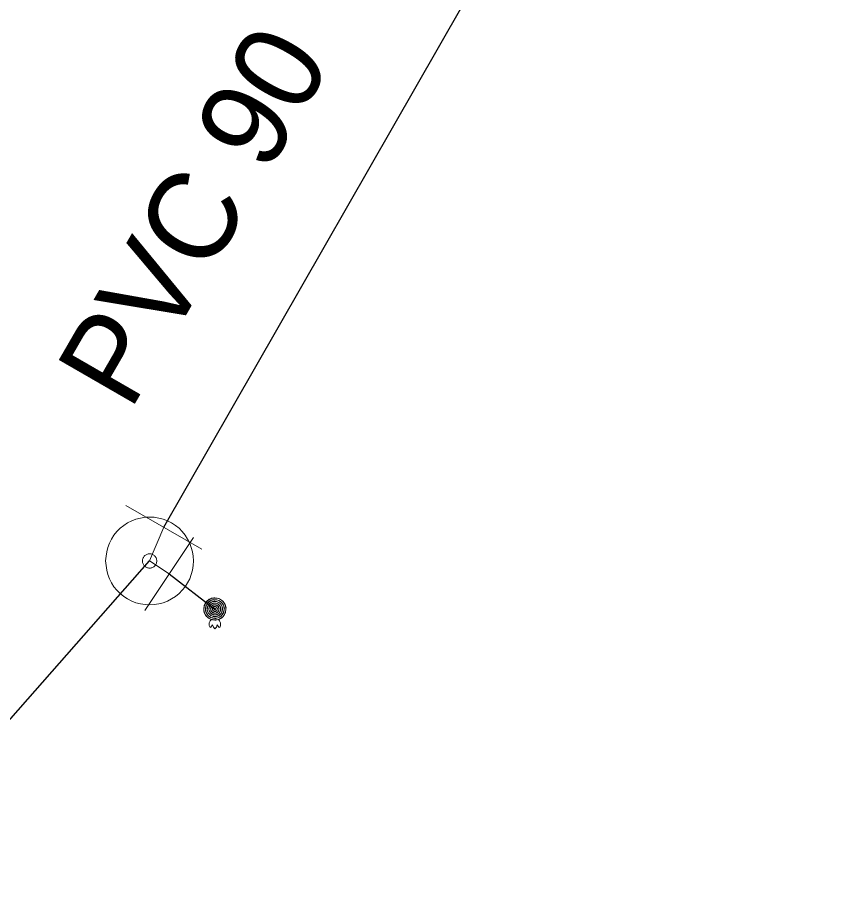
# Model space of a CAD drawing. Extents: x -683466 to -682479, y -996772 to -995963.
# Drawn here: x -682674.1 to -682664.75, y -996500.91 to -996490.91 of the extents above; entities that cross this region are included whole.
import ezdxf

# ---------------------------------------------------------------- set-up
doc = ezdxf.new("R2010")
doc.units = 0
doc.header["$LTSCALE"] = 0.4
doc.layers.add('1', color=7, linetype='Continuous')
for name, color, linetype, lineweight in [('14', 7, 'Continuous', 25), ('17', 7, 'Continuous', 25), ('34', 7, 'Continuous', 13), ('47', 7, 'Continuous', 13), ('9', 7, 'Continuous', 13)]:
    doc.layers.add(name, color=color, linetype=linetype, lineweight=lineweight)

msp = doc.modelspace()

# ---------------------------------------------------------------- linework, layer by layer
at = {"layer": '14', "lineweight": 13}
for q in [(-682672.44, -996496.719), (-682672.379, -996497.25)]:
    msp.add_line((-682672.602, -996497.102), q, dxfattribs=at)
at = {"layer": '17'}
msp.add_line((-682672.379, -996497.25), (-682671.859, -996497.649), dxfattribs=at)
for points in [[(-682672.44, -996496.719), (-682668.522, -996489.866), (-682664.75, -996485.199), (-682666.331, -996484.881)], [(-682688.782, -996515.794), (-682687.14, -996513.631), (-682672.602, -996497.102)]]:
    msp.add_lwpolyline(points, dxfattribs=at)
at = {"layer": '34'}
for p, q in [((-682672.874, -996496.471), (-682672.006, -996496.967)), ((-682672.102, -996496.833), (-682672.656, -996497.665))]:
    msp.add_line(p, q, dxfattribs=at)
at = {"layer": '47'}
for points in [[(-682672.102, -996497.102), (-682672.105, -996497.049), (-682672.113, -996496.997), (-682672.127, -996496.948), (-682672.144, -996496.899), (-682672.169, -996496.852), (-682672.198, -996496.808), (-682672.23, -996496.767), (-682672.267, -996496.73), (-682672.308, -996496.698), (-682672.352, -996496.669), (-682672.399, -996496.644), (-682672.448, -996496.627), (-682672.497, -996496.613), (-682672.549, -996496.605), (-682672.602, -996496.602), (-682672.654, -996496.605), (-682672.706, -996496.613), (-682672.757, -996496.627), (-682672.804, -996496.644), (-682672.852, -996496.669), (-682672.896, -996496.698), (-682672.936, -996496.73), (-682672.973, -996496.767), (-682673.007, -996496.808), (-682673.034, -996496.852), (-682673.059, -996496.899), (-682673.078, -996496.948), (-682673.09, -996496.997), (-682673.098, -996497.049), (-682673.102, -996497.102), (-682673.098, -996497.154), (-682673.09, -996497.206), (-682673.078, -996497.257), (-682673.059, -996497.304), (-682673.034, -996497.352), (-682673.007, -996497.396), (-682672.973, -996497.436), (-682672.936, -996497.473), (-682672.896, -996497.507), (-682672.852, -996497.534), (-682672.804, -996497.559), (-682672.757, -996497.578), (-682672.706, -996497.59), (-682672.654, -996497.598), (-682672.602, -996497.602), (-682672.549, -996497.598), (-682672.497, -996497.59), (-682672.448, -996497.578), (-682672.399, -996497.559), (-682672.352, -996497.534), (-682672.308, -996497.507), (-682672.267, -996497.473), (-682672.23, -996497.436), (-682672.198, -996497.396), (-682672.169, -996497.352), (-682672.144, -996497.304), (-682672.127, -996497.257), (-682672.113, -996497.206), (-682672.105, -996497.154)], [(-682672.519, -996497.102), (-682672.519, -996497.093), (-682672.522, -996497.085), (-682672.524, -996497.076), (-682672.527, -996497.068), (-682672.531, -996497.061), (-682672.536, -996497.054), (-682672.541, -996497.046), (-682672.546, -996497.041), (-682672.554, -996497.036), (-682672.561, -996497.031), (-682672.568, -996497.027), (-682672.576, -996497.024), (-682672.585, -996497.022), (-682672.593, -996497.019), (-682672.602, -996497.019), (-682672.61, -996497.019), (-682672.619, -996497.022), (-682672.627, -996497.024), (-682672.635, -996497.027), (-682672.642, -996497.031), (-682672.649, -996497.036), (-682672.657, -996497.041), (-682672.663, -996497.046), (-682672.669, -996497.054), (-682672.673, -996497.061), (-682672.676, -996497.068), (-682672.679, -996497.076), (-682672.681, -996497.085), (-682672.684, -996497.093), (-682672.684, -996497.102), (-682672.684, -996497.11), (-682672.681, -996497.119), (-682672.679, -996497.127), (-682672.676, -996497.135), (-682672.673, -996497.142), (-682672.669, -996497.149), (-682672.663, -996497.157), (-682672.657, -996497.163), (-682672.649, -996497.169), (-682672.642, -996497.173), (-682672.635, -996497.176), (-682672.627, -996497.179), (-682672.619, -996497.181), (-682672.61, -996497.184), (-682672.602, -996497.184), (-682672.593, -996497.184), (-682672.585, -996497.181), (-682672.576, -996497.179), (-682672.568, -996497.176), (-682672.561, -996497.173), (-682672.554, -996497.169), (-682672.546, -996497.163), (-682672.541, -996497.157), (-682672.536, -996497.149), (-682672.531, -996497.142), (-682672.527, -996497.135), (-682672.524, -996497.127), (-682672.522, -996497.119), (-682672.519, -996497.11)]]:
    msp.add_lwpolyline(points, close=True, dxfattribs=at)
at = {"layer": '9'}
for points in [[(-682671.859, -996497.522), (-682671.872, -996497.522), (-682671.885, -996497.524), (-682671.898, -996497.527), (-682671.91, -996497.532), (-682671.922, -996497.538), (-682671.933, -996497.545), (-682671.943, -996497.553), (-682671.953, -996497.563), (-682671.961, -996497.573), (-682671.968, -996497.584), (-682671.974, -996497.596), (-682671.979, -996497.608), (-682671.982, -996497.621), (-682671.984, -996497.634), (-682671.986, -996497.647), (-682671.985, -996497.66), (-682671.983, -996497.673), (-682671.98, -996497.686), (-682671.975, -996497.698), (-682671.969, -996497.71), (-682671.962, -996497.721), (-682671.954, -996497.731), (-682671.944, -996497.741), (-682671.934, -996497.749), (-682671.923, -996497.756), (-682671.911, -996497.762), (-682671.899, -996497.767), (-682671.886, -996497.77), (-682671.873, -996497.772), (-682671.86, -996497.774), (-682671.847, -996497.774), (-682671.834, -996497.772), (-682671.821, -996497.769), (-682671.809, -996497.764), (-682671.797, -996497.758), (-682671.786, -996497.751), (-682671.776, -996497.743), (-682671.766, -996497.733), (-682671.758, -996497.723), (-682671.751, -996497.712), (-682671.745, -996497.7), (-682671.74, -996497.688), (-682671.737, -996497.675), (-682671.735, -996497.662), (-682671.734, -996497.649), (-682671.734, -996497.636), (-682671.736, -996497.623), (-682671.739, -996497.61), (-682671.744, -996497.598), (-682671.75, -996497.586), (-682671.757, -996497.575), (-682671.765, -996497.565), (-682671.775, -996497.555), (-682671.785, -996497.547), (-682671.796, -996497.54), (-682671.808, -996497.534), (-682671.82, -996497.529), (-682671.833, -996497.526), (-682671.846, -996497.524)], [(-682671.859, -996497.776), (-682671.846, -996497.775), (-682671.833, -996497.773), (-682671.82, -996497.77), (-682671.808, -996497.765), (-682671.796, -996497.759), (-682671.785, -996497.752), (-682671.775, -996497.744), (-682671.765, -996497.734), (-682671.757, -996497.724), (-682671.75, -996497.713), (-682671.744, -996497.701), (-682671.739, -996497.689), (-682671.736, -996497.676), (-682671.734, -996497.663), (-682671.733, -996497.65), (-682671.732, -996497.637), (-682671.734, -996497.624), (-682671.737, -996497.611), (-682671.742, -996497.599), (-682671.748, -996497.587), (-682671.755, -996497.576), (-682671.763, -996497.566), (-682671.773, -996497.556), (-682671.783, -996497.548), (-682671.794, -996497.541), (-682671.806, -996497.535), (-682671.818, -996497.53), (-682671.831, -996497.527), (-682671.844, -996497.525), (-682671.857, -996497.524), (-682671.87, -996497.524), (-682671.883, -996497.526), (-682671.896, -996497.529), (-682671.908, -996497.534), (-682671.92, -996497.54), (-682671.931, -996497.547), (-682671.941, -996497.555), (-682671.951, -996497.565), (-682671.959, -996497.575), (-682671.966, -996497.586), (-682671.972, -996497.598), (-682671.977, -996497.61), (-682671.98, -996497.623), (-682671.982, -996497.636), (-682671.985, -996497.649), (-682671.984, -996497.662), (-682671.982, -996497.675), (-682671.979, -996497.688), (-682671.974, -996497.7), (-682671.968, -996497.712), (-682671.961, -996497.723), (-682671.953, -996497.733), (-682671.943, -996497.743), (-682671.933, -996497.751), (-682671.922, -996497.758), (-682671.91, -996497.764), (-682671.898, -996497.769), (-682671.885, -996497.772), (-682671.872, -996497.774)], [(-682671.859, -996497.543), (-682671.87, -996497.541), (-682671.881, -996497.543), (-682671.892, -996497.546), (-682671.902, -996497.55), (-682671.912, -996497.555), (-682671.921, -996497.561), (-682671.93, -996497.568), (-682671.938, -996497.576), (-682671.945, -996497.585), (-682671.951, -996497.594), (-682671.956, -996497.604), (-682671.96, -996497.614), (-682671.963, -996497.625), (-682671.966, -996497.636), (-682671.966, -996497.647), (-682671.966, -996497.658), (-682671.964, -996497.669), (-682671.961, -996497.68), (-682671.957, -996497.69), (-682671.952, -996497.7), (-682671.946, -996497.709), (-682671.939, -996497.718), (-682671.931, -996497.726), (-682671.922, -996497.733), (-682671.913, -996497.739), (-682671.903, -996497.744), (-682671.893, -996497.748), (-682671.882, -996497.751), (-682671.871, -996497.753), (-682671.86, -996497.754), (-682671.849, -996497.755), (-682671.838, -996497.753), (-682671.827, -996497.75), (-682671.817, -996497.746), (-682671.807, -996497.741), (-682671.798, -996497.735), (-682671.789, -996497.728), (-682671.781, -996497.72), (-682671.774, -996497.711), (-682671.768, -996497.702), (-682671.763, -996497.692), (-682671.759, -996497.682), (-682671.756, -996497.671), (-682671.754, -996497.66), (-682671.754, -996497.649), (-682671.753, -996497.638), (-682671.755, -996497.627), (-682671.758, -996497.616), (-682671.762, -996497.606), (-682671.767, -996497.596), (-682671.773, -996497.587), (-682671.78, -996497.578), (-682671.788, -996497.57), (-682671.797, -996497.563), (-682671.806, -996497.557), (-682671.816, -996497.552), (-682671.826, -996497.548), (-682671.837, -996497.545), (-682671.848, -996497.543)], [(-682671.859, -996497.756), (-682671.848, -996497.756), (-682671.837, -996497.754), (-682671.826, -996497.751), (-682671.816, -996497.747), (-682671.806, -996497.742), (-682671.797, -996497.736), (-682671.788, -996497.729), (-682671.78, -996497.721), (-682671.773, -996497.712), (-682671.767, -996497.703), (-682671.762, -996497.693), (-682671.758, -996497.683), (-682671.755, -996497.672), (-682671.753, -996497.661), (-682671.753, -996497.65), (-682671.751, -996497.639), (-682671.753, -996497.628), (-682671.756, -996497.617), (-682671.76, -996497.607), (-682671.765, -996497.597), (-682671.771, -996497.588), (-682671.778, -996497.579), (-682671.786, -996497.571), (-682671.795, -996497.564), (-682671.804, -996497.558), (-682671.814, -996497.553), (-682671.824, -996497.549), (-682671.835, -996497.546), (-682671.846, -996497.544), (-682671.857, -996497.544), (-682671.868, -996497.543), (-682671.879, -996497.545), (-682671.89, -996497.548), (-682671.9, -996497.552), (-682671.91, -996497.557), (-682671.919, -996497.563), (-682671.928, -996497.57), (-682671.936, -996497.578), (-682671.943, -996497.587), (-682671.949, -996497.596), (-682671.954, -996497.606), (-682671.958, -996497.616), (-682671.961, -996497.627), (-682671.963, -996497.638), (-682671.965, -996497.649), (-682671.965, -996497.66), (-682671.963, -996497.671), (-682671.96, -996497.682), (-682671.956, -996497.692), (-682671.951, -996497.702), (-682671.945, -996497.711), (-682671.938, -996497.72), (-682671.93, -996497.728), (-682671.921, -996497.735), (-682671.912, -996497.741), (-682671.902, -996497.746), (-682671.892, -996497.75), (-682671.881, -996497.753), (-682671.87, -996497.755)], [(-682671.859, -996497.561), (-682671.868, -996497.561), (-682671.877, -996497.562), (-682671.886, -996497.565), (-682671.894, -996497.568), (-682671.902, -996497.572), (-682671.91, -996497.577), (-682671.917, -996497.583), (-682671.923, -996497.589), (-682671.929, -996497.596), (-682671.934, -996497.604), (-682671.938, -996497.612), (-682671.941, -996497.62), (-682671.944, -996497.629), (-682671.945, -996497.638), (-682671.947, -996497.647), (-682671.946, -996497.656), (-682671.945, -996497.665), (-682671.942, -996497.674), (-682671.939, -996497.682), (-682671.935, -996497.69), (-682671.93, -996497.698), (-682671.924, -996497.705), (-682671.918, -996497.711), (-682671.911, -996497.717), (-682671.903, -996497.722), (-682671.895, -996497.726), (-682671.887, -996497.729), (-682671.878, -996497.732), (-682671.869, -996497.733), (-682671.86, -996497.735), (-682671.851, -996497.735), (-682671.842, -996497.734), (-682671.833, -996497.731), (-682671.825, -996497.728), (-682671.817, -996497.724), (-682671.809, -996497.719), (-682671.802, -996497.713), (-682671.796, -996497.707), (-682671.79, -996497.7), (-682671.785, -996497.692), (-682671.781, -996497.684), (-682671.778, -996497.676), (-682671.775, -996497.667), (-682671.774, -996497.658), (-682671.773, -996497.649), (-682671.773, -996497.64), (-682671.774, -996497.631), (-682671.777, -996497.622), (-682671.78, -996497.614), (-682671.784, -996497.606), (-682671.789, -996497.598), (-682671.795, -996497.591), (-682671.801, -996497.585), (-682671.808, -996497.579), (-682671.816, -996497.574), (-682671.824, -996497.57), (-682671.832, -996497.567), (-682671.841, -996497.564), (-682671.85, -996497.563)], [(-682671.859, -996497.737), (-682671.85, -996497.736), (-682671.841, -996497.735), (-682671.832, -996497.732), (-682671.824, -996497.729), (-682671.816, -996497.725), (-682671.808, -996497.72), (-682671.801, -996497.714), (-682671.795, -996497.708), (-682671.789, -996497.701), (-682671.784, -996497.693), (-682671.78, -996497.685), (-682671.777, -996497.677), (-682671.774, -996497.668), (-682671.773, -996497.659), (-682671.772, -996497.65), (-682671.771, -996497.641), (-682671.772, -996497.632), (-682671.775, -996497.623), (-682671.778, -996497.615), (-682671.782, -996497.607), (-682671.787, -996497.599), (-682671.793, -996497.592), (-682671.799, -996497.586), (-682671.806, -996497.58), (-682671.814, -996497.575), (-682671.822, -996497.571), (-682671.83, -996497.568), (-682671.839, -996497.565), (-682671.848, -996497.564), (-682671.857, -996497.563), (-682671.866, -996497.563), (-682671.875, -996497.564), (-682671.884, -996497.567), (-682671.892, -996497.57), (-682671.9, -996497.574), (-682671.908, -996497.579), (-682671.915, -996497.585), (-682671.921, -996497.591), (-682671.927, -996497.598), (-682671.932, -996497.606), (-682671.936, -996497.614), (-682671.939, -996497.622), (-682671.942, -996497.631), (-682671.943, -996497.64), (-682671.946, -996497.649), (-682671.945, -996497.658), (-682671.944, -996497.667), (-682671.941, -996497.676), (-682671.938, -996497.684), (-682671.934, -996497.692), (-682671.929, -996497.7), (-682671.923, -996497.707), (-682671.917, -996497.713), (-682671.91, -996497.719), (-682671.902, -996497.724), (-682671.894, -996497.728), (-682671.886, -996497.731), (-682671.877, -996497.734), (-682671.868, -996497.735)], [(-682671.859, -996497.581), (-682671.866, -996497.581), (-682671.873, -996497.582), (-682671.88, -996497.583), (-682671.886, -996497.586), (-682671.892, -996497.589), (-682671.898, -996497.593), (-682671.904, -996497.597), (-682671.909, -996497.602), (-682671.913, -996497.608), (-682671.917, -996497.614), (-682671.92, -996497.62), (-682671.923, -996497.626), (-682671.924, -996497.633), (-682671.927, -996497.64), (-682671.927, -996497.647), (-682671.927, -996497.654), (-682671.925, -996497.661), (-682671.924, -996497.668), (-682671.921, -996497.674), (-682671.918, -996497.681), (-682671.914, -996497.686), (-682671.91, -996497.692), (-682671.905, -996497.697), (-682671.899, -996497.701), (-682671.893, -996497.705), (-682671.887, -996497.708), (-682671.881, -996497.711), (-682671.874, -996497.713), (-682671.867, -996497.714), (-682671.86, -996497.715), (-682671.853, -996497.716), (-682671.846, -996497.715), (-682671.839, -996497.713), (-682671.833, -996497.71), (-682671.826, -996497.707), (-682671.821, -996497.703), (-682671.815, -996497.699), (-682671.81, -996497.694), (-682671.806, -996497.688), (-682671.802, -996497.683), (-682671.799, -996497.676), (-682671.796, -996497.67), (-682671.794, -996497.663), (-682671.793, -996497.656), (-682671.793, -996497.649), (-682671.793, -996497.642), (-682671.793, -996497.635), (-682671.795, -996497.628), (-682671.798, -996497.622), (-682671.801, -996497.616), (-682671.805, -996497.61), (-682671.809, -996497.604), (-682671.814, -996497.599), (-682671.82, -996497.595), (-682671.825, -996497.591), (-682671.832, -996497.588), (-682671.838, -996497.585), (-682671.845, -996497.584), (-682671.852, -996497.582)], [(-682671.859, -996497.717), (-682671.852, -996497.717), (-682671.845, -996497.715), (-682671.838, -996497.714), (-682671.832, -996497.711), (-682671.826, -996497.708), (-682671.82, -996497.704), (-682671.814, -996497.7), (-682671.809, -996497.695), (-682671.805, -996497.689), (-682671.801, -996497.683), (-682671.798, -996497.677), (-682671.795, -996497.671), (-682671.794, -996497.664), (-682671.792, -996497.657), (-682671.792, -996497.65), (-682671.79, -996497.643), (-682671.792, -996497.636), (-682671.793, -996497.629), (-682671.796, -996497.623), (-682671.799, -996497.616), (-682671.803, -996497.611), (-682671.807, -996497.605), (-682671.812, -996497.6), (-682671.818, -996497.596), (-682671.824, -996497.592), (-682671.83, -996497.589), (-682671.836, -996497.586), (-682671.843, -996497.584), (-682671.85, -996497.583), (-682671.857, -996497.583), (-682671.864, -996497.582), (-682671.871, -996497.583), (-682671.878, -996497.585), (-682671.884, -996497.588), (-682671.891, -996497.591), (-682671.896, -996497.595), (-682671.902, -996497.599), (-682671.907, -996497.604), (-682671.911, -996497.61), (-682671.915, -996497.615), (-682671.918, -996497.622), (-682671.921, -996497.628), (-682671.923, -996497.635), (-682671.924, -996497.642), (-682671.926, -996497.649), (-682671.926, -996497.656), (-682671.925, -996497.663), (-682671.923, -996497.67), (-682671.92, -996497.676), (-682671.917, -996497.682), (-682671.913, -996497.688), (-682671.909, -996497.694), (-682671.904, -996497.699), (-682671.898, -996497.703), (-682671.893, -996497.707), (-682671.886, -996497.71), (-682671.88, -996497.713), (-682671.873, -996497.714), (-682671.866, -996497.716)], [(-682671.859, -996497.602), (-682671.864, -996497.601), (-682671.869, -996497.601), (-682671.874, -996497.602), (-682671.878, -996497.604), (-682671.883, -996497.606), (-682671.887, -996497.609), (-682671.89, -996497.612), (-682671.894, -996497.616), (-682671.897, -996497.619), (-682671.9, -996497.623), (-682671.902, -996497.628), (-682671.904, -996497.632), (-682671.905, -996497.637), (-682671.907, -996497.642), (-682671.907, -996497.647), (-682671.907, -996497.652), (-682671.906, -996497.657), (-682671.905, -996497.662), (-682671.903, -996497.666), (-682671.901, -996497.671), (-682671.898, -996497.675), (-682671.895, -996497.679), (-682671.891, -996497.682), (-682671.888, -996497.685), (-682671.884, -996497.688), (-682671.879, -996497.69), (-682671.875, -996497.692), (-682671.87, -996497.693), (-682671.865, -996497.694), (-682671.86, -996497.695), (-682671.855, -996497.696), (-682671.85, -996497.695), (-682671.845, -996497.694), (-682671.841, -996497.692), (-682671.836, -996497.69), (-682671.832, -996497.687), (-682671.828, -996497.684), (-682671.825, -996497.681), (-682671.822, -996497.677), (-682671.819, -996497.673), (-682671.817, -996497.668), (-682671.815, -996497.664), (-682671.814, -996497.659), (-682671.813, -996497.654), (-682671.813, -996497.649), (-682671.813, -996497.644), (-682671.814, -996497.639), (-682671.814, -996497.634), (-682671.816, -996497.63), (-682671.818, -996497.625), (-682671.821, -996497.621), (-682671.824, -996497.618), (-682671.827, -996497.614), (-682671.831, -996497.611), (-682671.835, -996497.608), (-682671.84, -996497.606), (-682671.844, -996497.604), (-682671.849, -996497.603), (-682671.854, -996497.602)], [(-682671.859, -996497.697), (-682671.854, -996497.697), (-682671.849, -996497.696), (-682671.844, -996497.695), (-682671.84, -996497.693), (-682671.835, -996497.691), (-682671.831, -996497.688), (-682671.828, -996497.685), (-682671.824, -996497.681), (-682671.821, -996497.678), (-682671.818, -996497.674), (-682671.816, -996497.669), (-682671.814, -996497.665), (-682671.813, -996497.66), (-682671.812, -996497.655), (-682671.812, -996497.65), (-682671.81, -996497.645), (-682671.811, -996497.64), (-682671.812, -996497.635), (-682671.814, -996497.631), (-682671.816, -996497.626), (-682671.819, -996497.622), (-682671.822, -996497.618), (-682671.826, -996497.615), (-682671.829, -996497.612), (-682671.833, -996497.609), (-682671.838, -996497.607), (-682671.842, -996497.605), (-682671.847, -996497.604), (-682671.852, -996497.603), (-682671.857, -996497.603), (-682671.862, -996497.602), (-682671.867, -996497.603), (-682671.872, -996497.604), (-682671.876, -996497.606), (-682671.881, -996497.608), (-682671.885, -996497.611), (-682671.889, -996497.614), (-682671.892, -996497.617), (-682671.895, -996497.621), (-682671.898, -996497.625), (-682671.9, -996497.63), (-682671.902, -996497.634), (-682671.903, -996497.639), (-682671.904, -996497.644), (-682671.906, -996497.649), (-682671.906, -996497.654), (-682671.905, -996497.659), (-682671.904, -996497.664), (-682671.902, -996497.668), (-682671.9, -996497.673), (-682671.897, -996497.677), (-682671.894, -996497.68), (-682671.891, -996497.684), (-682671.887, -996497.687), (-682671.883, -996497.69), (-682671.878, -996497.692), (-682671.874, -996497.694), (-682671.869, -996497.695), (-682671.864, -996497.696)], [(-682671.859, -996497.622), (-682671.862, -996497.621), (-682671.865, -996497.62), (-682671.867, -996497.621), (-682671.87, -996497.622), (-682671.873, -996497.623), (-682671.875, -996497.625), (-682671.877, -996497.627), (-682671.879, -996497.629), (-682671.881, -996497.631), (-682671.883, -996497.633), (-682671.885, -996497.636), (-682671.886, -996497.639), (-682671.886, -996497.641), (-682671.887, -996497.644), (-682671.887, -996497.647), (-682671.887, -996497.65), (-682671.887, -996497.653), (-682671.886, -996497.656), (-682671.885, -996497.658), (-682671.884, -996497.661), (-682671.882, -996497.663), (-682671.88, -996497.666), (-682671.878, -996497.668), (-682671.876, -996497.669), (-682671.874, -996497.671), (-682671.871, -996497.672), (-682671.868, -996497.674), (-682671.866, -996497.674), (-682671.863, -996497.675), (-682671.86, -996497.676), (-682671.857, -996497.676), (-682671.854, -996497.676), (-682671.851, -996497.675), (-682671.849, -996497.674), (-682671.846, -996497.673), (-682671.844, -996497.671), (-682671.841, -996497.67), (-682671.839, -996497.668), (-682671.838, -996497.665), (-682671.836, -996497.663), (-682671.835, -996497.66), (-682671.834, -996497.658), (-682671.833, -996497.655), (-682671.833, -996497.652), (-682671.832, -996497.649), (-682671.833, -996497.646), (-682671.832, -996497.643), (-682671.834, -996497.641), (-682671.834, -996497.638), (-682671.835, -996497.635), (-682671.837, -996497.633), (-682671.838, -996497.631), (-682671.84, -996497.629), (-682671.843, -996497.627), (-682671.845, -996497.625), (-682671.848, -996497.624), (-682671.85, -996497.623), (-682671.853, -996497.622), (-682671.856, -996497.622)], [(-682671.859, -996497.677), (-682671.856, -996497.677), (-682671.853, -996497.677), (-682671.851, -996497.676), (-682671.848, -996497.675), (-682671.845, -996497.674), (-682671.843, -996497.672), (-682671.841, -996497.67), (-682671.839, -996497.668), (-682671.837, -996497.666), (-682671.835, -996497.664), (-682671.834, -996497.661), (-682671.833, -996497.658), (-682671.832, -996497.656), (-682671.832, -996497.653), (-682671.832, -996497.65), (-682671.831, -996497.647), (-682671.83, -996497.644), (-682671.831, -996497.641), (-682671.832, -996497.639), (-682671.833, -996497.636), (-682671.835, -996497.634), (-682671.837, -996497.631), (-682671.839, -996497.629), (-682671.841, -996497.628), (-682671.843, -996497.626), (-682671.846, -996497.625), (-682671.849, -996497.624), (-682671.851, -996497.623), (-682671.854, -996497.623), (-682671.857, -996497.622), (-682671.86, -996497.622), (-682671.863, -996497.622), (-682671.866, -996497.623), (-682671.868, -996497.624), (-682671.871, -996497.625), (-682671.873, -996497.627), (-682671.876, -996497.628), (-682671.878, -996497.63), (-682671.879, -996497.633), (-682671.881, -996497.635), (-682671.882, -996497.638), (-682671.883, -996497.64), (-682671.884, -996497.643), (-682671.884, -996497.646), (-682671.887, -996497.649), (-682671.886, -996497.652), (-682671.886, -996497.655), (-682671.885, -996497.657), (-682671.884, -996497.66), (-682671.883, -996497.663), (-682671.881, -996497.665), (-682671.88, -996497.667), (-682671.878, -996497.669), (-682671.875, -996497.671), (-682671.873, -996497.673), (-682671.87, -996497.674), (-682671.868, -996497.675), (-682671.865, -996497.676), (-682671.862, -996497.676)], [(-682671.859, -996497.641), (-682671.861, -996497.64), (-682671.861, -996497.64), (-682671.861, -996497.641), (-682671.863, -996497.641), (-682671.864, -996497.64), (-682671.864, -996497.642), (-682671.864, -996497.642), (-682671.866, -996497.642), (-682671.866, -996497.642), (-682671.867, -996497.643), (-682671.867, -996497.645), (-682671.867, -996497.645), (-682671.868, -996497.645), (-682671.868, -996497.647), (-682671.868, -996497.647), (-682671.868, -996497.648), (-682671.868, -996497.649), (-682671.867, -996497.649), (-682671.867, -996497.65), (-682671.867, -996497.652), (-682671.866, -996497.652), (-682671.866, -996497.652), (-682671.865, -996497.653), (-682671.865, -996497.653), (-682671.864, -996497.655), (-682671.863, -996497.655), (-682671.862, -996497.656), (-682671.862, -996497.656), (-682671.861, -996497.656), (-682671.86, -996497.656), (-682671.859, -996497.657), (-682671.858, -996497.657), (-682671.858, -996497.657), (-682671.857, -996497.656), (-682671.856, -996497.656), (-682671.855, -996497.655), (-682671.855, -996497.655), (-682671.854, -996497.654), (-682671.854, -996497.654), (-682671.853, -996497.653), (-682671.853, -996497.652), (-682671.852, -996497.651), (-682671.852, -996497.651), (-682671.852, -996497.65), (-682671.852, -996497.649), (-682671.852, -996497.648), (-682671.852, -996497.647), (-682671.852, -996497.647), (-682671.853, -996497.646), (-682671.852, -996497.645), (-682671.854, -996497.644), (-682671.854, -996497.644), (-682671.854, -996497.643), (-682671.854, -996497.643), (-682671.856, -996497.642), (-682671.857, -996497.642), (-682671.858, -996497.642), (-682671.858, -996497.641), (-682671.859, -996497.641)], [(-682671.859, -996497.658), (-682671.858, -996497.658), (-682671.857, -996497.658), (-682671.857, -996497.657), (-682671.856, -996497.657), (-682671.855, -996497.657), (-682671.854, -996497.656), (-682671.854, -996497.656), (-682671.853, -996497.655), (-682671.853, -996497.655), (-682671.852, -996497.654), (-682671.852, -996497.653), (-682671.852, -996497.652), (-682671.851, -996497.652), (-682671.851, -996497.651), (-682671.851, -996497.65), (-682671.851, -996497.649), (-682671.851, -996497.648), (-682671.852, -996497.648), (-682671.852, -996497.647), (-682671.85, -996497.646), (-682671.852, -996497.645), (-682671.852, -996497.645), (-682671.852, -996497.644), (-682671.852, -996497.644), (-682671.853, -996497.643), (-682671.854, -996497.643), (-682671.855, -996497.642), (-682671.855, -996497.642), (-682671.856, -996497.642), (-682671.857, -996497.642), (-682671.858, -996497.642), (-682671.859, -996497.642), (-682671.859, -996497.642), (-682671.86, -996497.642), (-682671.861, -996497.642), (-682671.862, -996497.643), (-682671.862, -996497.643), (-682671.863, -996497.644), (-682671.863, -996497.644), (-682671.864, -996497.645), (-682671.865, -996497.646), (-682671.867, -996497.647), (-682671.867, -996497.647), (-682671.867, -996497.648), (-682671.867, -996497.649), (-682671.867, -996497.65), (-682671.867, -996497.651), (-682671.867, -996497.651), (-682671.866, -996497.652), (-682671.866, -996497.653), (-682671.865, -996497.654), (-682671.865, -996497.654), (-682671.864, -996497.655), (-682671.864, -996497.655), (-682671.863, -996497.656), (-682671.862, -996497.656), (-682671.861, -996497.656), (-682671.861, -996497.657), (-682671.86, -996497.657)]]:
    msp.add_lwpolyline(points, close=True, dxfattribs=at)
for points in [[(-682671.913, -996497.861), (-682671.925, -996497.835), (-682671.925, -996497.808), (-682671.913, -996497.782), (-682671.898, -996497.769)], [(-682671.804, -996497.861), (-682671.793, -996497.835), (-682671.793, -996497.808), (-682671.805, -996497.782), (-682671.819, -996497.769)], [(-682671.886, -996497.831), (-682671.906, -996497.855), (-682671.913, -996497.861)], [(-682671.886, -996497.831), (-682671.876, -996497.857), (-682671.859, -996497.874)], [(-682671.832, -996497.831), (-682671.841, -996497.857), (-682671.859, -996497.874)], [(-682671.832, -996497.831), (-682671.812, -996497.855), (-682671.804, -996497.861)]]:
    msp.add_lwpolyline(points, dxfattribs=at)

# ---------------------------------------------------------------- texts
at = {"layer": '1'}
msp.add_text('PVC 90', height=1, rotation=60, dxfattribs=at).set_placement((-682672.824, -996495.408))

doc.saveas('drawing.dxf')
